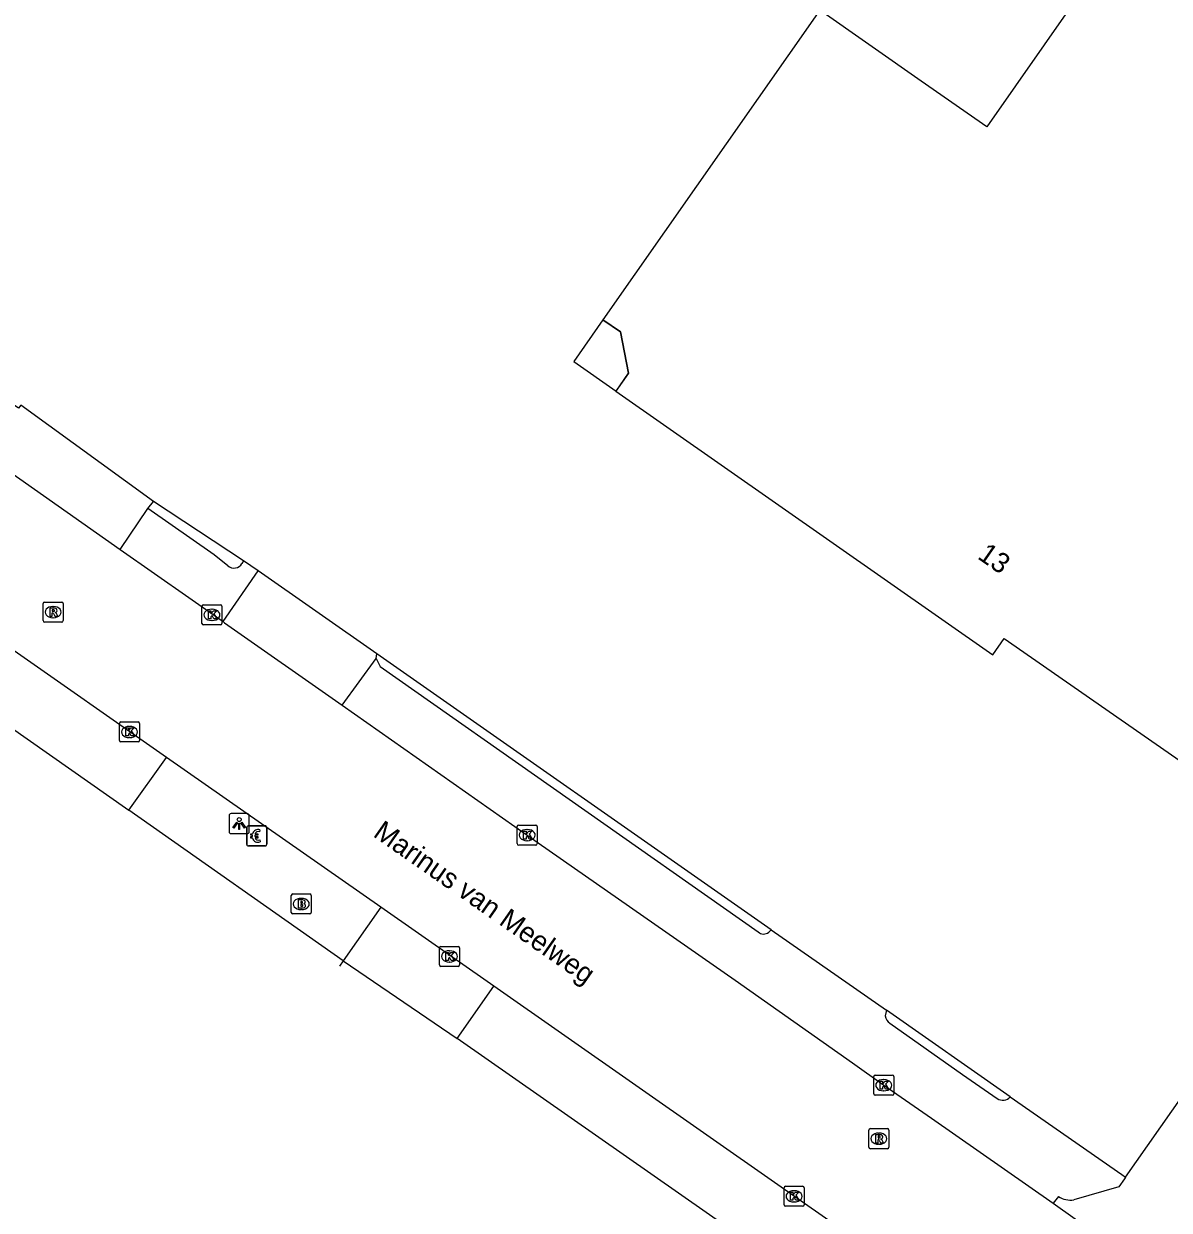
# Model space of a CAD drawing. Extents: x 155018 to 156648, y 383980 to 385733.
# Drawn here: x 155319.7 to 155376.9, y 385075.2 to 385134.4 of the extents above; entities that cross this region are included whole.
import ezdxf

# ---------------------------------------------------------------- set-up
doc = ezdxf.new("R2010")
doc.units = 0
for name, color, linetype in [('IMGEO_Betaalautomaat', 7, 'Continuous'), ('IMGEO_Brandkraan', 7, 'Continuous'), ('IMGEO_Hek', 7, 'Continuous'), ('IMGEO_Kolk', 7, 'Continuous'), ('IMGEO_Lichtpunt', 7, 'Continuous'), ('IMGEO_Openbare_ruimte_label', 7, 'Continuous'), ('IMGEO_Pand', 7, 'Continuous'), ('IMGEO_Pand_nummerreeks', 7, 'Continuous'), ('IMGEO_Pand_overbouw', 7, 'Continuous'), ('IMGEO_Parkeervlak_open', 7, 'Continuous'), ('IMGEO_Rijbaan_lokaal_gesloten', 7, 'Continuous'), ('IMGEO_Rijbaan_lokaal_open', 7, 'Continuous'), ('IMGEO_Rioolput', 7, 'Continuous'), ('IMGEO_Voetpad_open', 7, 'Continuous')]:
    doc.layers.add(name, color=color, linetype=linetype)

msp = doc.modelspace()

# ---------------------------------------------------------------- linework, layer by layer
at = {"layer": 'IMGEO_Betaalautomaat'}
for p, q in [((155330.846, 385093.447), (155330.846, 385094.288)), ((155330.846, 385094.288), (155330.846, 385093.447)), ((155330.921, 385094.371), (155331.762, 385094.371)), ((155331.762, 385094.371), (155330.921, 385094.371)), ((155331.129, 385093.835), (155331.129, 385093.903)), ((155331.25, 385093.903), (155331.25, 385093.835)), ((155331.508, 385094.176), (155331.491, 385094.076)), ((155331.845, 385094.297), (155331.845, 385093.456)), ((155331.845, 385093.456), (155331.845, 385094.297)), ((155331.771, 385093.372), (155330.93, 385093.372)), ((155330.93, 385093.372), (155331.771, 385093.372)), ((155331.495, 385093.67), (155331.517, 385093.583))]:
    msp.add_line(p, q, dxfattribs=at)
for points in [[(155331.129, 385093.903), (155331.06, 385093.903), (155331.06, 385093.972), (155331.139, 385093.972)], [(155331.134, 385093.766), (155331.06, 385093.766), (155331.06, 385093.835), (155331.129, 385093.835)], [(155331.261, 385093.972), (155331.408, 385093.972), (155331.408, 385093.903), (155331.25, 385093.903)], [(155331.25, 385093.835), (155331.408, 385093.835), (155331.408, 385093.766), (155331.264, 385093.766)]]:
    msp.add_lwpolyline(points, dxfattribs=at)
for centre, radius, start, end in [((155330.924, 385094.294), 0.0779, 92.4484, 184.28452), ((155330.924, 385094.294), 0.0779, 92.4484, 184.28452), ((155331.422, 385093.896), 0.293, 73.01398, 165.01395), ((155331.428, 385093.909), 0.179, 69.32359, 159.56827), ((155331.768, 385094.294), 0.0779, 2.4484, 94.28452), ((155331.768, 385094.294), 0.0779, 2.4484, 94.28452), ((155330.924, 385093.45), 0.0779, 182.4484, 274.28452), ((155330.924, 385093.45), 0.0779, 182.4484, 274.28452), ((155331.395, 385093.821), 0.267, 191.80956, 297.03891), ((155331.428, 385093.836), 0.179, 202.76249, 291.86925), ((155331.768, 385093.45), 0.0779, 272.4484, 4.28452), ((155331.768, 385093.45), 0.0779, 272.4484, 4.28452)]:
    msp.add_arc(centre, radius, start, end, dxfattribs=at)
at = {"layer": 'IMGEO_Brandkraan'}
for p, q in [((155333.068, 385090.049), (155333.068, 385090.901)), ((155333.143, 385090.975), (155333.995, 385090.975)), ((155334.069, 385090.901), (155334.069, 385090.049)), ((155333.556, 385090.755), (155333.581, 385090.755)), ((155333.995, 385089.975), (155333.143, 385089.975)), ((155333.579, 385090.195), (155333.554, 385090.195))]:
    msp.add_line(p, q, dxfattribs=at)
for points in [[(155333.068, 385090.049), (155333.068, 385090.901)], [(155333.143, 385090.975), (155333.995, 385090.975)], [(155334.069, 385090.901), (155334.069, 385090.049)], [(155333.416, 385090.675), (155333.416, 385090.275), (155333.629, 385090.275)], [(155333.647, 385090.675), (155333.416, 385090.675)], [(155333.595, 385090.594), (155333.541, 385090.594), (155333.541, 385090.518)], [(155333.541, 385090.518), (155333.594, 385090.518)], [(155333.603, 385090.442), (155333.541, 385090.442), (155333.541, 385090.361)], [(155333.541, 385090.361), (155333.603, 385090.361)], [(155333.995, 385089.975), (155333.143, 385089.975)]]:
    msp.add_lwpolyline(points, dxfattribs=at)
for centre, radius, start, end in [((155333.145, 385090.899), 0.0765, 91.55205, 178.44795), ((155333.145, 385090.899), 0.0765, 91.55205, 178.44795), ((155333.993, 385090.899), 0.0765, 1.55205, 88.44795), ((155333.993, 385090.899), 0.0765, 1.55205, 88.44795), ((155333.596, 385090.556), 0.0379, 267.82845, 90.93552), ((155333.604, 385090.401), 0.0404, 269.87594, 90.50774), ((155333.635, 385090.526), 0.251, 268.66757, 293.53466), ((155333.651, 385090.53), 0.145, 59.4692, 91.53667), ((155333.676, 385090.577), 0.0922, 285.51372, 58.15012), ((155333.681, 385090.385), 0.105, 301.31148, 78.98903), ((155333.145, 385090.051), 0.0765, 181.55205, 268.44795), ((155333.145, 385090.051), 0.0765, 181.55205, 268.44795), ((155333.993, 385090.051), 0.0765, 271.55205, 358.44795), ((155333.993, 385090.051), 0.0765, 271.55205, 358.44795)]:
    msp.add_arc(centre, radius, start, end, dxfattribs=at)
for centre, major_axis, ratio, start_param, end_param in [((155333.555, 385090.475), (-0.387, 0.002), 0.722429, 4.712389, 7.853982), ((155333.58, 385090.475), (-0.39, 0.002), 0.717154, 1.570796, 4.712389)]:
    msp.add_ellipse(centre, major_axis=major_axis, ratio=ratio, start_param=start_param, end_param=end_param, dxfattribs=at)
at = {"layer": 'IMGEO_Hek'}
msp.add_lwpolyline([(155335.658, 385087.641), (155335.469, 385087.372)], dxfattribs=at)
at = {"layer": 'IMGEO_Kolk'}
for p, q in [((155328.612, 385104.477), (155328.612, 385105.329)), ((155328.687, 385105.403), (155329.539, 385105.403)), ((155329.1, 385105.183), (155329.125, 385105.183)), ((155329.613, 385105.329), (155329.613, 385104.477)), ((155329.123, 385104.623), (155329.098, 385104.623)), ((155329.539, 385104.403), (155328.687, 385104.403)), ((155324.498, 385098.633), (155324.498, 385099.485)), ((155324.573, 385099.559), (155325.425, 385099.559)), ((155324.986, 385099.339), (155325.011, 385099.339)), ((155325.499, 385099.485), (155325.499, 385098.633)), ((155325.425, 385098.559), (155324.573, 385098.559)), ((155325.009, 385098.779), (155324.984, 385098.779)), ((155344.414, 385094.411), (155345.266, 385094.411)), ((155344.339, 385093.485), (155344.339, 385094.337)), ((155344.827, 385094.191), (155344.852, 385094.191)), ((155345.34, 385094.337), (155345.34, 385093.485)), ((155345.266, 385093.411), (155344.414, 385093.411)), ((155344.85, 385093.631), (155344.825, 385093.631)), ((155340.461, 385087.432), (155340.461, 385088.284)), ((155340.536, 385088.358), (155341.388, 385088.358)), ((155340.949, 385088.138), (155340.974, 385088.138)), ((155341.462, 385088.284), (155341.462, 385087.432)), ((155341.388, 385087.358), (155340.536, 385087.358)), ((155340.972, 385087.578), (155340.947, 385087.578)), ((155362.124, 385081.006), (155362.124, 385081.858)), ((155362.199, 385081.932), (155363.051, 385081.932)), ((155362.612, 385081.712), (155362.637, 385081.712)), ((155363.125, 385081.858), (155363.125, 385081.006)), ((155363.051, 385080.932), (155362.199, 385080.932)), ((155362.635, 385081.152), (155362.61, 385081.152)), ((155357.651, 385075.461), (155357.651, 385076.313)), ((155357.726, 385076.387), (155358.578, 385076.387)), ((155358.139, 385076.167), (155358.164, 385076.167)), ((155358.652, 385076.313), (155358.652, 385075.461)), ((155358.162, 385075.607), (155358.137, 385075.607)), ((155358.578, 385075.387), (155357.726, 385075.387))]:
    msp.add_line(p, q, dxfattribs=at)
for points in [[(155328.612, 385104.477), (155328.612, 385105.329)], [(155328.687, 385105.403), (155329.539, 385105.403)], [(155328.933, 385105.103), (155329.056, 385105.103), (155329.056, 385104.952), (155329.186, 385105.103), (155329.35, 385105.103), (155329.204, 385104.952), (155329.357, 385104.703), (155329.205, 385104.703), (155329.12, 385104.867), (155329.056, 385104.8), (155329.056, 385104.703), (155328.933, 385104.703), (155328.933, 385105.103)], [(155329.613, 385105.329), (155329.613, 385104.477)], [(155329.539, 385104.403), (155328.687, 385104.403)], [(155324.498, 385098.633), (155324.498, 385099.485)], [(155324.573, 385099.559), (155325.425, 385099.559)], [(155324.819, 385099.259), (155324.942, 385099.259), (155324.942, 385099.108), (155325.072, 385099.259), (155325.236, 385099.259), (155325.09, 385099.108), (155325.243, 385098.859), (155325.091, 385098.859), (155325.006, 385099.023), (155324.942, 385098.956), (155324.942, 385098.859), (155324.819, 385098.859), (155324.819, 385099.259)], [(155325.499, 385099.485), (155325.499, 385098.633)], [(155325.425, 385098.559), (155324.573, 385098.559)], [(155344.414, 385094.411), (155345.266, 385094.411)], [(155344.339, 385093.485), (155344.339, 385094.337)], [(155344.66, 385094.111), (155344.783, 385094.111), (155344.783, 385093.96), (155344.913, 385094.111), (155345.077, 385094.111), (155344.931, 385093.96), (155345.084, 385093.711), (155344.932, 385093.711), (155344.847, 385093.875), (155344.783, 385093.808), (155344.783, 385093.711), (155344.66, 385093.711), (155344.66, 385094.111)], [(155345.34, 385094.337), (155345.34, 385093.485)], [(155345.266, 385093.411), (155344.414, 385093.411)], [(155340.461, 385087.432), (155340.461, 385088.284)], [(155340.536, 385088.358), (155341.388, 385088.358)], [(155340.782, 385088.058), (155340.905, 385088.058), (155340.905, 385087.907), (155341.035, 385088.058), (155341.199, 385088.058), (155341.053, 385087.907), (155341.206, 385087.658), (155341.054, 385087.658), (155340.969, 385087.822), (155340.905, 385087.755), (155340.905, 385087.658), (155340.782, 385087.658), (155340.782, 385088.058)], [(155341.462, 385088.284), (155341.462, 385087.432)], [(155341.388, 385087.358), (155340.536, 385087.358)], [(155362.124, 385081.006), (155362.124, 385081.858)], [(155362.199, 385081.932), (155363.051, 385081.932)], [(155362.445, 385081.632), (155362.568, 385081.632), (155362.568, 385081.481), (155362.698, 385081.632), (155362.862, 385081.632), (155362.716, 385081.481), (155362.869, 385081.232), (155362.717, 385081.232), (155362.632, 385081.396), (155362.568, 385081.329), (155362.568, 385081.232), (155362.445, 385081.232), (155362.445, 385081.632)], [(155363.125, 385081.858), (155363.125, 385081.006)], [(155363.051, 385080.932), (155362.199, 385080.932)], [(155357.651, 385075.461), (155357.651, 385076.313)], [(155357.726, 385076.387), (155358.578, 385076.387)], [(155357.972, 385076.087), (155358.095, 385076.087), (155358.095, 385075.936), (155358.225, 385076.087), (155358.389, 385076.087), (155358.243, 385075.936), (155358.396, 385075.687), (155358.244, 385075.687), (155358.159, 385075.851), (155358.095, 385075.784), (155358.095, 385075.687), (155357.972, 385075.687), (155357.972, 385076.087)], [(155358.652, 385076.313), (155358.652, 385075.461)], [(155358.578, 385075.387), (155357.726, 385075.387)]]:
    msp.add_lwpolyline(points, dxfattribs=at)
for centre, start, end in [((155328.689, 385105.327), 91.55205, 178.44795), ((155328.689, 385105.327), 91.55205, 178.44795), ((155329.537, 385105.327), 1.55205, 88.44795), ((155329.537, 385105.327), 1.55205, 88.44795), ((155328.689, 385104.479), 181.55205, 268.44795), ((155328.689, 385104.479), 181.55205, 268.44795), ((155329.537, 385104.479), 271.55205, 358.44795), ((155329.537, 385104.479), 271.55205, 358.44795), ((155324.575, 385099.483), 91.55205, 178.44795), ((155324.575, 385099.483), 91.55205, 178.44795), ((155325.423, 385099.483), 1.55205, 88.44795), ((155325.423, 385099.483), 1.55205, 88.44795), ((155324.575, 385098.635), 181.55205, 268.44795), ((155324.575, 385098.635), 181.55205, 268.44795), ((155325.423, 385098.635), 271.55205, 358.44795), ((155325.423, 385098.635), 271.55205, 358.44795), ((155344.416, 385094.335), 91.55205, 178.44795), ((155344.416, 385094.335), 91.55205, 178.44795), ((155345.264, 385094.335), 1.55205, 88.44795), ((155345.264, 385094.335), 1.55205, 88.44795), ((155344.416, 385093.487), 181.55205, 268.44795), ((155344.416, 385093.487), 181.55205, 268.44795), ((155345.264, 385093.487), 271.55205, 358.44795), ((155345.264, 385093.487), 271.55205, 358.44795), ((155340.538, 385088.282), 91.55205, 178.44795), ((155340.538, 385088.282), 91.55205, 178.44795), ((155341.386, 385088.282), 1.55205, 88.44795), ((155341.386, 385088.282), 1.55205, 88.44795), ((155340.538, 385087.434), 181.55205, 268.44795), ((155340.538, 385087.434), 181.55205, 268.44795), ((155341.386, 385087.434), 271.55205, 358.44795), ((155341.386, 385087.434), 271.55205, 358.44795), ((155362.201, 385081.856), 91.55205, 178.44795), ((155362.201, 385081.856), 91.55205, 178.44795), ((155363.049, 385081.856), 1.55205, 88.44795), ((155363.049, 385081.856), 1.55205, 88.44795), ((155362.201, 385081.008), 181.55205, 268.44795), ((155362.201, 385081.008), 181.55205, 268.44795), ((155363.049, 385081.008), 271.55205, 358.44795), ((155363.049, 385081.008), 271.55205, 358.44795), ((155357.728, 385076.311), 91.55205, 178.44795), ((155357.728, 385076.311), 91.55205, 178.44795), ((155358.576, 385076.311), 1.55205, 88.44795), ((155358.576, 385076.311), 1.55205, 88.44795), ((155357.728, 385075.463), 181.55205, 268.44795), ((155357.728, 385075.463), 181.55205, 268.44795), ((155358.576, 385075.463), 271.55205, 358.44795), ((155358.576, 385075.463), 271.55205, 358.44795)]:
    msp.add_arc(centre, 0.0765, start, end, dxfattribs=at)
for centre, major_axis, ratio, start_param, end_param in [((155329.099, 385104.903), (-0.387, 0.002), 0.722429, 4.712389, 7.853982), ((155329.124, 385104.903), (-0.39, 0.002), 0.717154, 1.570796, 4.712389), ((155324.985, 385099.059), (-0.387, 0.002), 0.722429, 4.712389, 7.853982), ((155325.01, 385099.059), (-0.39, 0.002), 0.717154, 1.570796, 4.712389), ((155344.826, 385093.911), (-0.387, 0.002), 0.722429, 4.712389, 7.853982), ((155344.851, 385093.911), (-0.39, 0.002), 0.717154, 1.570796, 4.712389), ((155340.948, 385087.858), (-0.387, 0.002), 0.722429, 4.712389, 7.853982), ((155340.973, 385087.858), (-0.39, 0.002), 0.717154, 1.570796, 4.712389), ((155362.611, 385081.432), (-0.387, 0.002), 0.722429, 4.712389, 7.853982), ((155362.636, 385081.432), (-0.39, 0.002), 0.717154, 1.570796, 4.712389), ((155358.138, 385075.887), (-0.387, 0.002), 0.722429, 4.712389, 7.853982), ((155358.163, 385075.887), (-0.39, 0.002), 0.717154, 1.570796, 4.712389)]:
    msp.add_ellipse(centre, major_axis=major_axis, ratio=ratio, start_param=start_param, end_param=end_param, dxfattribs=at)
at = {"layer": 'IMGEO_Lichtpunt'}
for p, q in [((155330.874, 385094.985), (155330.066, 385094.985)), ((155330.874, 385094.985), (155330.066, 385094.985)), ((155329.972, 385094.89), (155329.972, 385094.083)), ((155329.972, 385094.89), (155329.972, 385094.083)), ((155330.968, 385094.083), (155330.968, 385094.89)), ((155330.968, 385094.083), (155330.968, 385094.89)), ((155330.066, 385093.989), (155330.874, 385093.989)), ((155330.066, 385093.989), (155330.874, 385093.989))]:
    msp.add_line(p, q, dxfattribs=at)
for points in [[(155330.346, 385094.554), (155330.385, 385094.526), (155330.197, 385094.264), (155330.159, 385094.291), (155330.346, 385094.554)], [(155330.448, 385094.506), (155330.495, 385094.506), (155330.495, 385094.184), (155330.448, 385094.184), (155330.448, 385094.506)], [(155330.558, 385094.526), (155330.596, 385094.553), (155330.783, 385094.291), (155330.744, 385094.263), (155330.558, 385094.526)]]:
    msp.add_lwpolyline(points, dxfattribs=at)
msp.add_circle((155330.471, 385094.688), 0.0994, dxfattribs=at)
for centre, start, end in [((155330.066, 385094.89), 90, 180), ((155330.066, 385094.89), 90, 180), ((155330.874, 385094.89), 0, 90), ((155330.874, 385094.89), 0, 90), ((155330.066, 385094.083), 180, 270), ((155330.066, 385094.083), 180, 270), ((155330.874, 385094.083), 270, 0), ((155330.874, 385094.083), 270, 360)]:
    msp.add_arc(centre, 0.0946, start, end, dxfattribs=at)
at = {"layer": 'IMGEO_Pand'}
msp.add_lwpolyline([(155442.008, 385172.848), (155443.274, 385174.657), (155413.901, 385195.202), (155370.632, 385133.346), (155367.766, 385129.249), (155364.489, 385131.542), (155359.431, 385135.082), (155348.617, 385119.628), (155349.496, 385119.02), (155349.893, 385116.961), (155349.266, 385116.068), (155368.071, 385102.911), (155368.632, 385103.714), (155385.157, 385092.221), (155424.544, 385148.026), (155428.297, 385153.343)], dxfattribs=at)
at = {"layer": 'IMGEO_Pand_overbouw'}
msp.add_lwpolyline([(155349.269, 385116.072), (155349.893, 385116.961), (155349.496, 385119.02), (155348.617, 385119.628), (155347.158, 385117.543)], close=True, dxfattribs=at)
at = {"layer": 'IMGEO_Parkeervlak_open'}
for points in [[(155357.012, 385089.192), (155362.767, 385085.177)], [(155368.936, 385080.858), (155374.497, 385076.979), (155374.69, 385076.843)]]:
    msp.add_lwpolyline(points, dxfattribs=at)
at = {"layer": 'IMGEO_Rijbaan_lokaal_gesloten'}
for points in [[(155317.594, 385113.031), (155324.528, 385108.168)], [(155324.528, 385108.168), (155329.668, 385104.564)], [(155329.668, 385104.564), (155329.745, 385104.51), (155335.606, 385100.394)], [(155326.847, 385097.791), (155318.912, 385103.338)], [(155335.606, 385100.394), (155344.839, 385093.91), (155355.211, 385086.676), (155361.07, 385082.554), (155362.624, 385081.432), (155365.015, 385079.792), (155371.069, 385075.541)], [(155337.534, 385090.321), (155326.847, 385097.791)], [(155343.17, 385086.381), (155337.534, 385090.321)], [(155381.966, 385059.233), (155343.17, 385086.381)], [(155371.069, 385075.541), (155373.162, 385074.071), (155378.611, 385070.279)]]:
    msp.add_lwpolyline(points, dxfattribs=at)
at = {"layer": 'IMGEO_Rijbaan_lokaal_open'}
for points in [[(155326.192, 385110.553), (155319.575, 385115.362), (155319.464, 385115.209), (155319.238, 385115.369)], [(155325.912, 385110.206), (155326.192, 385110.553)], [(155324.528, 385108.168), (155325.912, 385110.206)], [(155329.668, 385104.564), (155331.41, 385107.093)], [(155337.343, 385102.951), (155331.41, 385107.093)], [(155335.606, 385100.394), (155337.298, 385102.717)], [(155337.298, 385102.717), (155337.343, 385102.951)], [(155317.041, 385100.717), (155324.962, 385095.154)], [(155324.962, 385095.154), (155326.847, 385097.791)], [(155337.534, 385090.321), (155335.658, 385087.641)], [(155335.658, 385087.641), (155341.349, 385083.758)], [(155341.349, 385083.758), (155343.17, 385086.381)], [(155374.69, 385076.843), (155377.552, 385080.911), (155381.071, 385078.436), (155379.97, 385076.651), (155379.055, 385073.827), (155378.305, 385071.512)], [(155374.69, 385076.843), (155374.635, 385076.765), (155374.349, 385076.359), (155372.1, 385075.71)], [(155371.346, 385075.878), (155371.069, 385075.541)]]:
    msp.add_lwpolyline(points, dxfattribs=at)
msp.add_arc((155371.929, 385076.719), 1.023, 235.2589, 279.61912, dxfattribs=at)
at = {"layer": 'IMGEO_Rioolput'}
for p, q in [((155320.689, 385104.614), (155320.689, 385105.466)), ((155320.764, 385105.54), (155321.616, 385105.54)), ((155321.177, 385105.32), (155321.202, 385105.32)), ((155321.69, 385105.466), (155321.69, 385104.614)), ((155321.616, 385104.54), (155320.764, 385104.54)), ((155321.2, 385104.76), (155321.175, 385104.76)), ((155361.881, 385078.336), (155361.881, 385079.188)), ((155361.956, 385079.262), (155362.808, 385079.262)), ((155362.369, 385079.042), (155362.394, 385079.042)), ((155362.882, 385079.188), (155362.882, 385078.336)), ((155362.392, 385078.482), (155362.367, 385078.482)), ((155362.808, 385078.262), (155361.956, 385078.262))]:
    msp.add_line(p, q, dxfattribs=at)
for points in [[(155320.689, 385104.614), (155320.689, 385105.466)], [(155320.764, 385105.54), (155321.616, 385105.54)], [(155321.278, 385105.238), (155321.026, 385105.24), (155321.026, 385104.84)], [(155321.204, 385105.159), (155321.15, 385105.159), (155321.15, 385105.078)], [(155321.15, 385105.078), (155321.202, 385105.078)], [(155321.69, 385105.466), (155321.69, 385104.614)], [(155321.616, 385104.54), (155320.764, 385104.54)], [(155321.026, 385104.84), (155321.15, 385104.84), (155321.15, 385105.002), (155321.161, 385105.002)], [(155321.208, 385104.973), (155321.279, 385104.84), (155321.419, 385104.84), (155321.354, 385104.966)], [(155361.881, 385078.336), (155361.881, 385079.188)], [(155361.956, 385079.262), (155362.808, 385079.262)], [(155362.882, 385079.188), (155362.882, 385078.336)], [(155362.47, 385078.96), (155362.218, 385078.962), (155362.218, 385078.562)], [(155362.218, 385078.562), (155362.342, 385078.562), (155362.342, 385078.724), (155362.353, 385078.724)], [(155362.396, 385078.881), (155362.342, 385078.881), (155362.342, 385078.8)], [(155362.342, 385078.8), (155362.394, 385078.8)], [(155362.4, 385078.695), (155362.471, 385078.562), (155362.611, 385078.562), (155362.546, 385078.688)], [(155362.808, 385078.262), (155361.956, 385078.262)]]:
    msp.add_lwpolyline(points, dxfattribs=at)
for centre, radius, start, end in [((155320.766, 385105.464), 0.0765, 91.55205, 178.44795), ((155320.766, 385105.464), 0.0765, 91.55205, 178.44795), ((155321.186, 385105.267), 0.19, 274.7715, 282.96867), ((155321.21, 385105.063), 0.0964, 77.00612, 93.18647), ((155321.224, 385105.12), 0.0378, 276.66336, 79.67722), ((155321.277, 385105.128), 0.109, 350.36119, 89.41601), ((155321.275, 385105.128), 0.112, 277.58423, 350.98172), ((155321.614, 385105.464), 0.0765, 1.55205, 88.44795), ((155321.614, 385105.464), 0.0765, 1.55205, 88.44795), ((155320.766, 385104.616), 0.0765, 181.55205, 268.44795), ((155320.766, 385104.616), 0.0765, 181.55205, 268.44795), ((155321.16, 385104.949), 0.0533, 26.02933, 88.69889), ((155321.259, 385104.913), 0.108, 29.51342, 73.79051), ((155321.614, 385104.616), 0.0765, 271.55205, 358.44795), ((155321.614, 385104.616), 0.0765, 271.55205, 358.44795), ((155361.958, 385079.186), 0.0765, 91.55205, 178.44795), ((155361.958, 385079.186), 0.0765, 91.55205, 178.44795), ((155362.806, 385079.186), 0.0765, 1.55205, 88.44795), ((155362.806, 385079.186), 0.0765, 1.55205, 88.44795), ((155362.352, 385078.671), 0.0533, 26.02933, 88.69889), ((155362.378, 385078.989), 0.19, 274.7715, 282.96867), ((155362.402, 385078.785), 0.0964, 77.00612, 93.18647), ((155362.416, 385078.842), 0.0378, 276.66336, 79.67722), ((155362.469, 385078.85), 0.109, 350.36119, 89.41601), ((155362.467, 385078.85), 0.112, 277.58423, 350.98172), ((155362.451, 385078.635), 0.108, 29.51342, 73.79051), ((155361.958, 385078.338), 0.0765, 181.55205, 268.44795), ((155361.958, 385078.338), 0.0765, 181.55205, 268.44795), ((155362.806, 385078.338), 0.0765, 271.55205, 358.44795), ((155362.806, 385078.338), 0.0765, 271.55205, 358.44795)]:
    msp.add_arc(centre, radius, start, end, dxfattribs=at)
for centre, major_axis, ratio, start_param, end_param in [((155321.176, 385105.04), (-0.387, 0.002), 0.722429, 4.712389, 7.853982), ((155321.201, 385105.04), (-0.39, 0.002), 0.717154, 1.570796, 4.712389), ((155362.368, 385078.762), (-0.387, 0.002), 0.722429, 4.712389, 7.853982), ((155362.393, 385078.762), (-0.39, 0.002), 0.717154, 1.570796, 4.712389)]:
    msp.add_ellipse(centre, major_axis=major_axis, ratio=ratio, start_param=start_param, end_param=end_param, dxfattribs=at)
at = {"layer": 'IMGEO_Voetpad_open'}
for points in [[(155330.684, 385107.602), (155326.192, 385110.553)], [(155329.909, 385107.346), (155329.231, 385107.894), (155325.912, 385110.206)], [(155330.684, 385107.602), (155330.608, 385107.462)], [(155331.41, 385107.093), (155330.684, 385107.602)], [(155337.298, 385102.717), (155337.497, 385102.322), (155356.362, 385089.08)], [(155357.012, 385089.192), (155337.343, 385102.951)], [(155335.658, 385087.641), (155324.962, 385095.154)], [(155356.885, 385089.061), (155357.012, 385089.192)], [(155362.767, 385085.177), (155362.702, 385084.889)], [(155368.936, 385080.858), (155362.767, 385085.177)], [(155362.934, 385084.519), (155366.55, 385081.973), (155368.277, 385080.771)], [(155380.151, 385056.63), (155341.349, 385083.758)]]:
    msp.add_lwpolyline(points, dxfattribs=at)
for centre, radius, start, end in [((155330.207, 385107.711), 0.472, 230.75711, 328.08777), ((155356.635, 385089.381), 0.406, 227.79453, 308.04432), ((155363.157, 385084.916), 0.455, 183.44073, 240.73692), ((155368.56, 385081.169), 0.488, 234.63219, 320.409)]:
    msp.add_arc(centre, radius, start, end, dxfattribs=at)

# ---------------------------------------------------------------- texts
at = {"layer": 'IMGEO_Openbare_ruimte_label'}
msp.add_text('Marinus van Meelweg', height=1, rotation=325.0549, dxfattribs=at).set_placement((155337.103, 385093.878))
at = {"layer": 'IMGEO_Pand_nummerreeks'}
msp.add_text('13', height=1, rotation=325.18171, dxfattribs=at).set_placement((155367.253, 385107.743))

doc.saveas('drawing.dxf')
